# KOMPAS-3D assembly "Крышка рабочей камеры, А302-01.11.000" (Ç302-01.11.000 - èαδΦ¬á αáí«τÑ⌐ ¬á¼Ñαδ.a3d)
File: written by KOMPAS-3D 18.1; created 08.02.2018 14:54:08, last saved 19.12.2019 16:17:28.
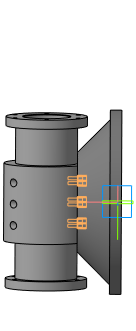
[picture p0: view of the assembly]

Document properties: Автор: Милов; Полное имя файла: D:\Мембранные насосы\Мембранный электропривод\А302-00.00.000 - ASTRA-302 (МЭ200)\3Д ПВХ\А302-01.11.000 - Крышка рабочей камеры.a3d

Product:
- Part/product: Крышка рабочей камеры  | designation А302-01.11.000  | pos. 0
    Масса: 3.3695
    Раздел спецификации: Сборочные единицы
    Форматы листов документа: A3
    source file: А302-01.11.000 - Крышка рабочей камеры.cdw
  - Component [detail]: Отвод ПВХ 45@1~ @2~50 арт.HIV050  | pos. 3  | Масса: 0.188602; Раздел спецификации: Прочие изделия; source file: Отработка\Отвод ПВХ 45гр 50 арт.HIV050.m3d
  - Component [detail]: Отвод ПВХ 90@1~ @2~50 арт.GIV050  | pos. 4  | Масса: 0.204878; Раздел спецификации: Прочие изделия; source file: Отработка\Отвод ПВХ 90гр 50 арт.GIV050.m3d
  - Component [assembly]: Корпус  | designation А302-01.31.000  | qty 2  | pos. 2  | Масса: 0.623932; Раздел спецификации: Сборочные единицы; Форматы листов документа: A3; source file: А302-01.31.000 - Корпус.a3d, А302-01.31.000 - Корпус.cdw
  - Component [assembly]: Крышка  | designation А302-01.12.000  | pos. 1  | Материал: Полипропилен  ГОСТ 26996-86 (density 900 kg/m3); Масса: 2.54616; Раздел спецификации: Сборочные единицы; Форматы листов документа: A3; source file: А302-01.12.000 - Крышка.a3d, А302-01.12.000 - Крышка.cdw
- Part/product: Крышка рабочей камеры  | designation А302-02.11.000  | pos. 0
    Материал: Поливинилхлорид (density 1350 kg/m3)
    Масса: 5.98117
    Раздел спецификации: Сборочные единицы
    Форматы листов документа: A3
    source file: А302-02.00.000 - ASTRA-302 (МЭ200)\А302-02.11.000 - Крышка рабочей камеры.cdw
  - Component [assembly]: Крышка  | designation А302-02.12.000  | pos. 1  | Материал: Полипропилен  ГОСТ 26996-86 (density 900 kg/m3); Масса: 2.64473; Раздел спецификации: Сборочные единицы; Форматы листов документа: A3
  - Component [assembly]: Корпус  | designation А302-01.31.000  | pos. 2  | Раздел спецификации: Сборочные единицы; Форматы листов документа: A3; source file: А302-01.31.000 - Корпус.a3d
  - Component [detail]: Корпус со встроенными стаканами  | designation А302-02.31.000  | pos. 13  | Материал: Поливинилхлорид (density 1350 kg/m3); Масса: 3.18846; Раздел спецификации: Детали; Форматы листов документа: A3; source file: ..\Чертежи ПВХ\А302-02.31.000 - Корпус со встроенными стаканами.cdw, А302-01.31.000 - Корпус со встроенными стаканами.m3d, А302-02.00.000 - ASTRA-302 (МЭ200)\А302-02.31.000 - Корпус со встроенными стаканами.cdw
  - Component [detail]: Труба PVC-U 50*3,7  | pos. 12  | Масса: 0.14798; Раздел спецификации: Детали; source file: ..\..\..\..\1 ПКИ 3D\ПВХ фитинги, трубы\Труба PVC-U 50 3,7.m3d
- Part/product: Крышка рабочей камеры  | designation А302-03.11.000  | pos. 0
    Материал: Поливинилхлорид (density 1350 kg/m3)
    Масса: 5.69363
    Раздел спецификации: Сборочные единицы
    Форматы листов документа: A3
    source file: ..\..\А302-03.00.000 - ASTRA-302 (МЭ200)\А302-03.11.000 - Крышка рабочей камеры.cdw, ..\Чертежи ПВХ\А302-02.11.000 - Крышка рабочей камеры.cdw, ..\Чертежи Полипропилен\А302-03.11.000 - Крышка рабочей камеры.cdw
  - Component [standard]: Шайба C.6.21 ГОСТ 11371-78  | qty 6  | pos. 184  | Материал: Сталь 12Х18Н10Т ГОСТ 5632-72 (density 1000 kg/m3); Масса: 0.00099; Раздел спецификации: Стандартные изделия; Рассекать на разрезах: no; additional columns: Сталь 12Х18Н10Т ГОСТ 5632-72
  - Component [standard]: Шайба 6 30Х13 ГОСТ 6402-70  | qty 6  | pos. 190  | Материал: Сталь 30Х13 ГОСТ 5632-72 (density 1000 kg/m3); Масса: 0.000376; Раздел спецификации: Стандартные изделия; Рассекать на разрезах: no; additional columns: Сталь 30Х13 ГОСТ 5632-72
  - Component [detail]: Винт с цилиндрической головкой / и вн. шестигранником / DIN 912-М6х80-А2-70  | qty 6  | pos. 197  | Масса: 0.0238493; Раздел спецификации: Стандартные изделия; source file: ..\..\..\..\2 Стандартные изделия 3D\Винты\Din 912\Винт DIN 912-М6х100-А2-70.m3d
  - Component [detail]: Корпус со встроенными стаканами  | designation А302-03.31.000  | pos. 13  | Материал: Поливинилхлорид (density 1350 kg/m3); Масса: 2.60942; Раздел спецификации: Детали; Форматы листов документа: A3; source file: ..\..\А302-03.00.000 - ASTRA-302 (МЭ200)\А302-03.31.000 - Корпус со встроенными стаканами.cdw, ..\Чертежи Полипропилен\А302-03.31.000 - Корпус со встроенными стаканами.cdw, А302-01.31.000 - Корпус со встроенными стаканами.m3d
  - Component [assembly]: Крышка  | designation А302-03.12.000  | pos. 1  | Материал: Полипропилен  ГОСТ 26996-86 (density 900 kg/m3); Масса: 2.93292; Раздел спецификации: Сборочные единицы; Форматы листов документа: A3; source file: ..\..\А302-03.00.000 - ASTRA-302 (МЭ200)\А302-03.12.000 - Крышка.cdw, ..\Чертежи Полипропилен\А302-03.12.000 - Крышка.cdw, А302-01.12.000 - Крышка.a3d

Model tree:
1. Сечение поверхностью:1  (with: Вырезать элемент выдавливания:9, Операция выдавливания:9, Кинематическая операция:1, Вырезать элемент выдавливания:10)  (labels: Отработка\Отвод ПВХ 90гр 50 арт.GIV050.m3d; Отработка\Отвод ПВХ 45гр 50 арт.HIV050.m3d; А302-01.31.000 - Корпус.a3d)
2. Массив по сетке:1  (6 pattern instances)
     Шаг 1 = 88; Угол раствора = 90; Шаг 2 = 35

Referenced files in D:\Мембранные насосы\Мембранный электропривод\А302-00.00.000 - ASTRA-302 (МЭ200)\3Д ПВХ\: А302-01.12.000 - Крышка.a3d, А302-01.12.000 - Крышка.cdw, А302-01.31.000 - Корпус.a3d, А302-01.31.000 - Корпус.cdw, А302-01.31.000 - Корпус со встроенными стаканами.m3d, А302-01.11.000 - Крышка рабочей камеры.cdw
Referenced files in D:\Мембранные насосы\Мембранный электропривод\А302-00.00.000 - ASTRA-302 (МЭ200)\3Д ПВХ\Отработка\: Отвод ПВХ 90гр 50 арт.GIV050.m3d, Отвод ПВХ 45гр 50 арт.HIV050.m3d
Referenced files in D:\1 ПКИ 3D\ПВХ фитинги, трубы\: Труба PVC-U 50 3,7.m3d
Referenced files in D:\Мембранные насосы\Мембранный электропривод\А302-00.00.000 - ASTRA-302 (МЭ200)\3Д ПВХ\А302-02.00.000 - ASTRA-302 (МЭ200)\: А302-02.31.000 - Корпус со встроенными стаканами.cdw
Referenced files in D:\Мембранные насосы\Мембранный электропривод\А302-00.00.000 - ASTRA-302 (МЭ200)\Чертежи ПВХ\: А302-02.31.000 - Корпус со встроенными стаканами.cdw
Referenced files in D:\Мембранные насосы\Мембранный электропривод\А302-00.00.000 - ASTRA-302 (МЭ200)\3Д ПВХ\..\..\А302-03.00.000 - ASTRA-302 (МЭ200)\: А302-03.31.000 - Корпус со встроенными стаканами.cdw, А302-03.12.000 - Крышка.cdw
Referenced files in D:\Мембранные насосы\Мембранный электропривод\А302-00.00.000 - ASTRA-302 (МЭ200)\3Д ПВХ\..\Чертежи Полипропилен\: А302-03.31.000 - Корпус со встроенными стаканами.cdw, А302-03.12.000 - Крышка.cdw
Referenced files in D:\2 Стандартные изделия 3D\Винты\Din 912\: Винт DIN 912-М6х100-А2-70.m3d
Referenced files in C:\Program Files\ASCON\KOMPAS-3D v18\Libs\PartLib\DATA\VAULT\methods\kompas\3d\: PLib_Washer_1_712.m3d, PLib_Washer_2_712.m3d
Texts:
  Винт с цилиндрической головкой
  и вн. шестигранником
  DIN 912-М6х80-А2-70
